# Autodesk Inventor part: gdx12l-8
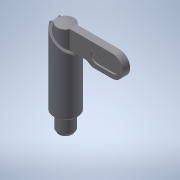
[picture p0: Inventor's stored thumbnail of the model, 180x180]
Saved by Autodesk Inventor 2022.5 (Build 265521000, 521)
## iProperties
Created: 2016-12
Part Number: gdx12l-8
Material: 一般
Document SubType Name: Modeling
Designer: imaocorp
Density: 1 g/cm^3
Appearance: 既定
Author: imaocorp
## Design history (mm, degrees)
node "gdx12l-8.x_t1"
node "gdx12l-8"
node "Base1"
